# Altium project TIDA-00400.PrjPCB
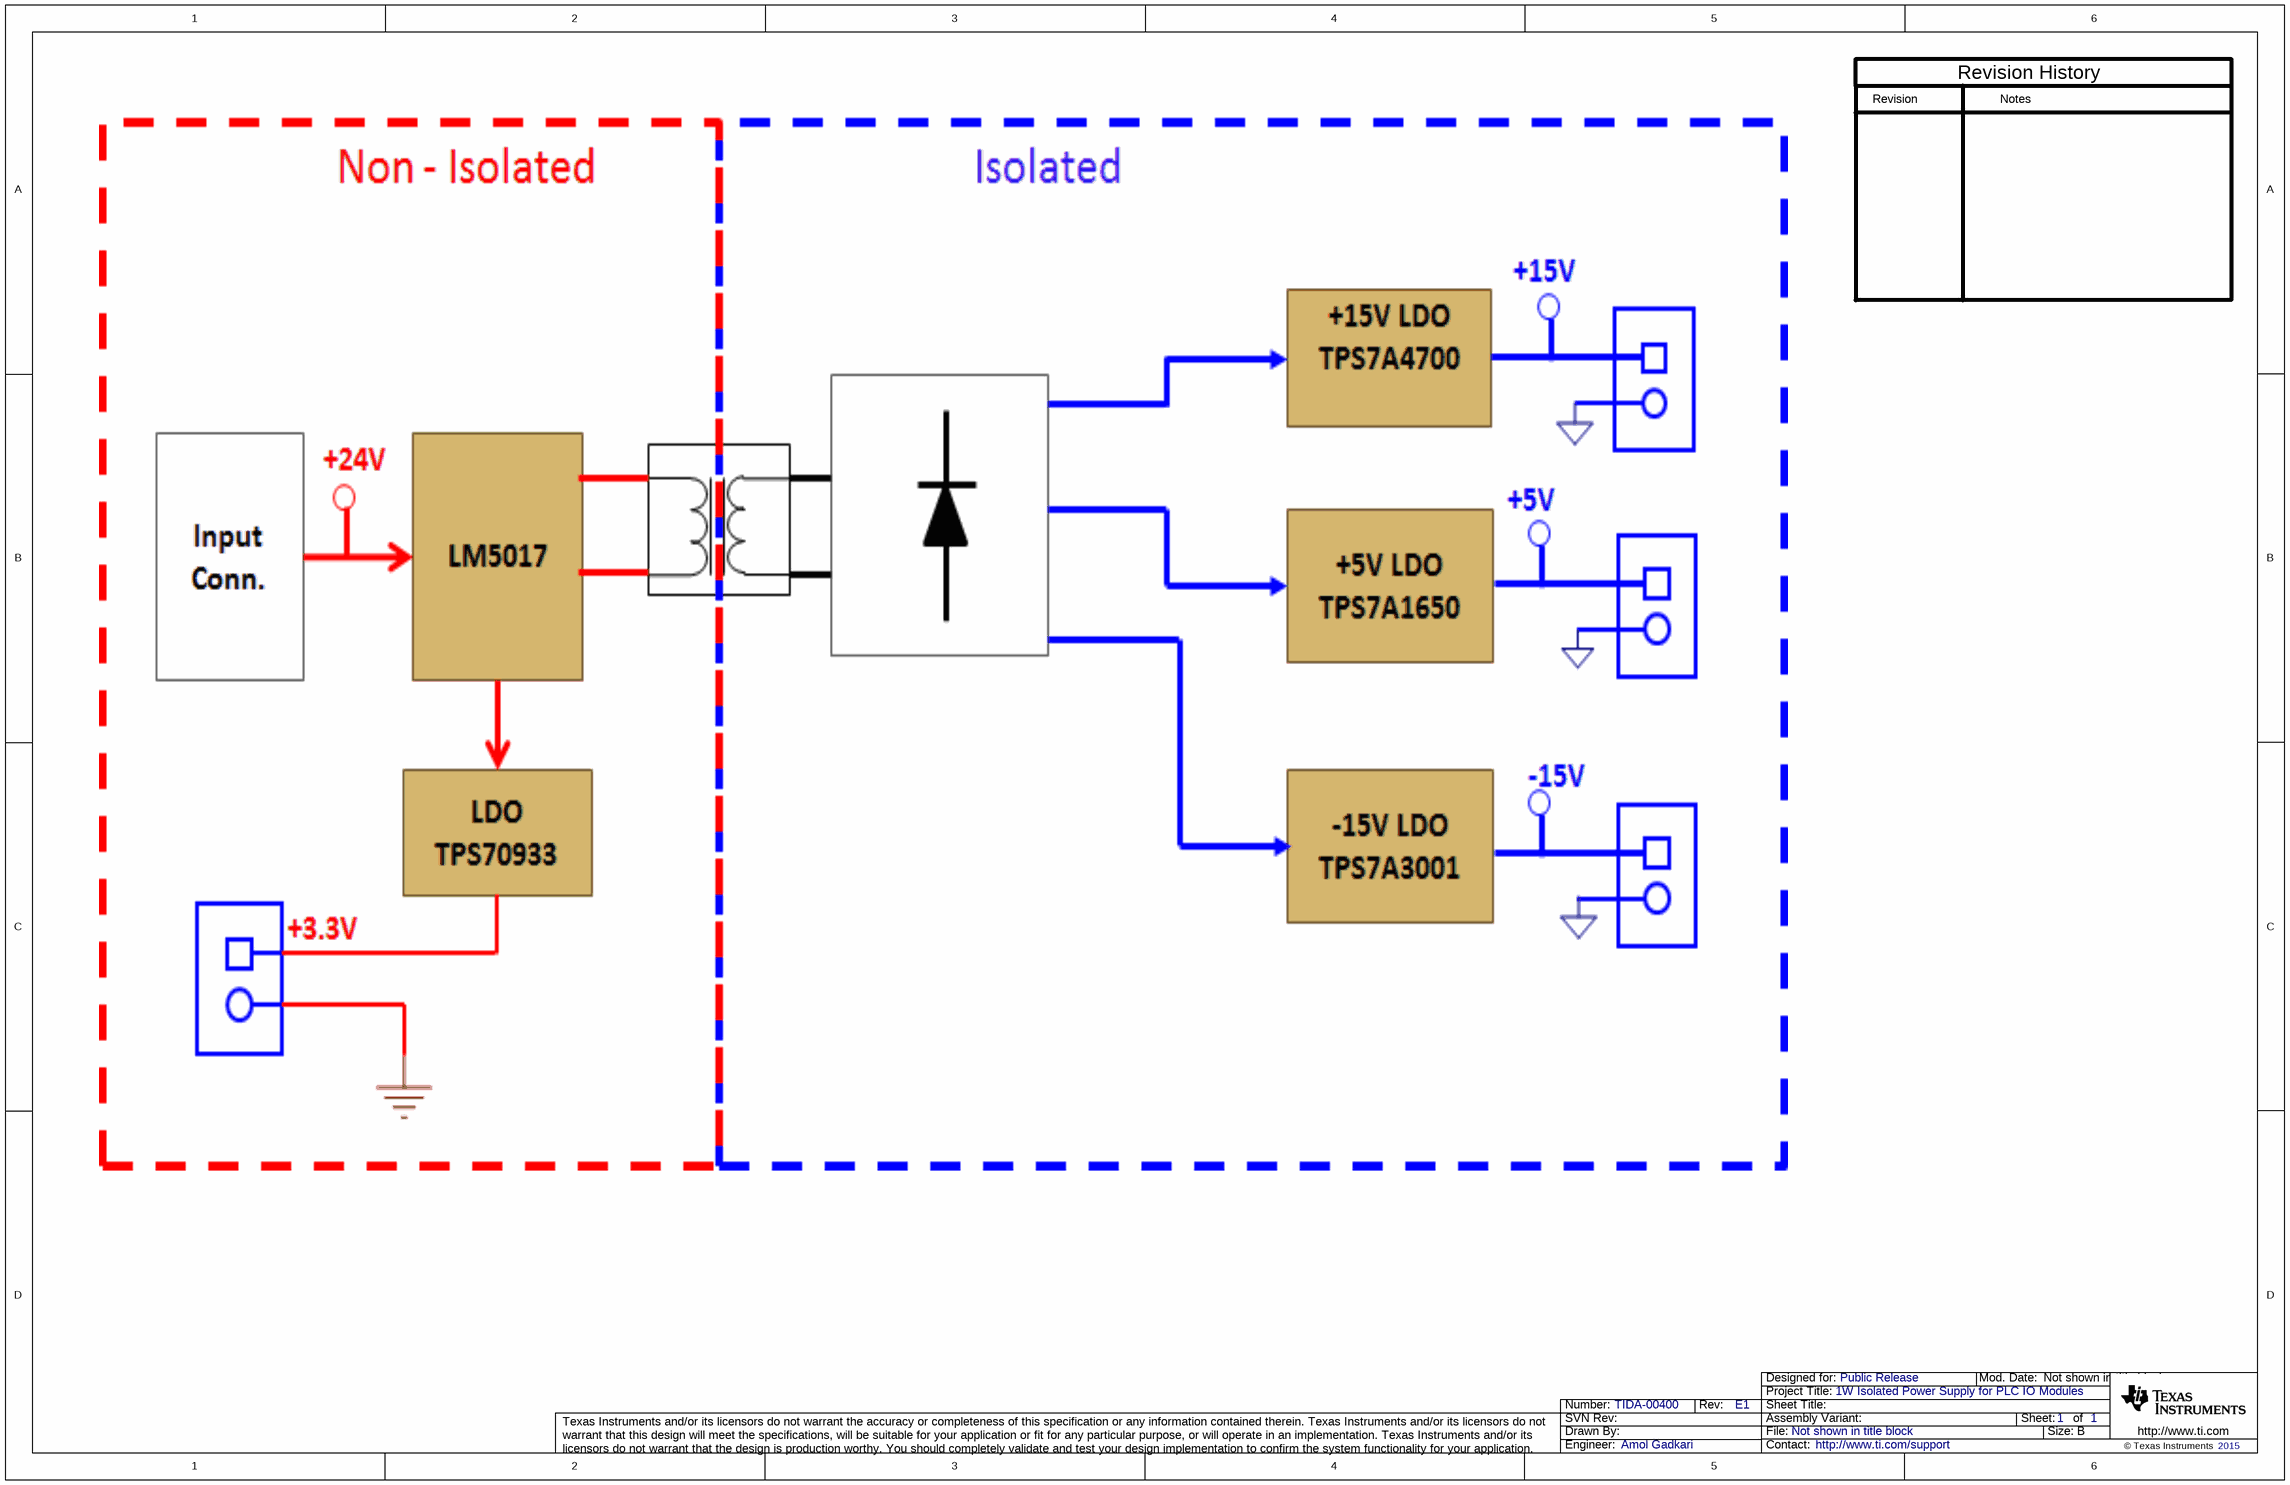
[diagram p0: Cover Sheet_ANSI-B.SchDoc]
CopyrightYear: 2015; PCB_Layout: Sharanu; PCB_Rev: E1; PRJ_Customer: Public Release; PRJ_Engineer: Amol Gadkari; PRJ_Number: TIDA-00400; PRJ_Title: 1W Isolated Power Supply for PLC IO Modules; SCH_Rev: E1; TechSupport: http://www.ti.com/support
4 sheets, 124 parts. Net scope: global (net labels, ports and power ports of the same name join across sheets).
Board file: TIDA-00400.PcbDoc
Sheets:
  Cover Sheet_ANSI-B.SchDoc
  Isolated_Flybuck_PS.SchDoc
  Post Regulated LDO.SchDoc
  Hardware_ANSI-B.SchDoc

## Sheet Cover Sheet_ANSI-B.SchDoc
size 431 x 279 mm; Date: Not shown in title block; ApprovedBy: Not shown in title block; CheckedBy: Not shown in title block; Author: Not shown in title block; CompanyName: Not shown in title block; Engineer: Not shown in title block; Organization: Not shown in title block; Address1: Not shown in title block; Address2: Not shown in title block; Address3: Not shown in title block; Address4: Not shown in title block; DocumentNumber: 1; Revision: Use project parameter SCH_Rev; SheetNumber: 1; SheetTotal: 1; PageSetup: Record=PageOptions|CenterHorizontal=True|CenterVertical=True|PrintScale=1.00|XCorrection=1.00|YCorrection=1.00|PrintKind=0|BorderSize=5000000|LeftOffset=0|BottomOffset=0|Orientation=2|PaperLength=1000|PaperWidth=1000|Scale=100|PaperSource=15|PrintQuality=600|MediaType=1|DitherType=10|PaperKind=Letter|PrintScaleMode=1

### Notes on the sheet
- Revision
- Notes
- Revision History

## Sheet Isolated_Flybuck_PS.SchDoc
size 431 x 279 mm; Date: Not shown in title block; ApprovedBy: Not shown in title block; CheckedBy: Not shown in title block; Author: Not shown in title block; CompanyName: Not shown in title block; Engineer: Not shown in title block; Organization: Not shown in title block; Address1: Not shown in title block; Address2: Not shown in title block; Address3: Not shown in title block; Address4: Not shown in title block; DocumentNumber: 1; Revision: Use project parameter SCH_Rev; SheetNumber: 1; SheetTotal: 1; PageSetup: Record=PageOptions|CenterHorizontal=True|CenterVertical=True|PrintScale=1.00|XCorrection=1.00|YCorrection=1.00|PrintKind=0|BorderSize=5000000|LeftOffset=0|BottomOffset=0|Orientation=2|PaperLength=1000|PaperWidth=1000|Scale=100|PaperSource=15|PrintQuality=600|MediaType=1|DitherType=10|PaperKind=Letter|PrintScaleMode=1
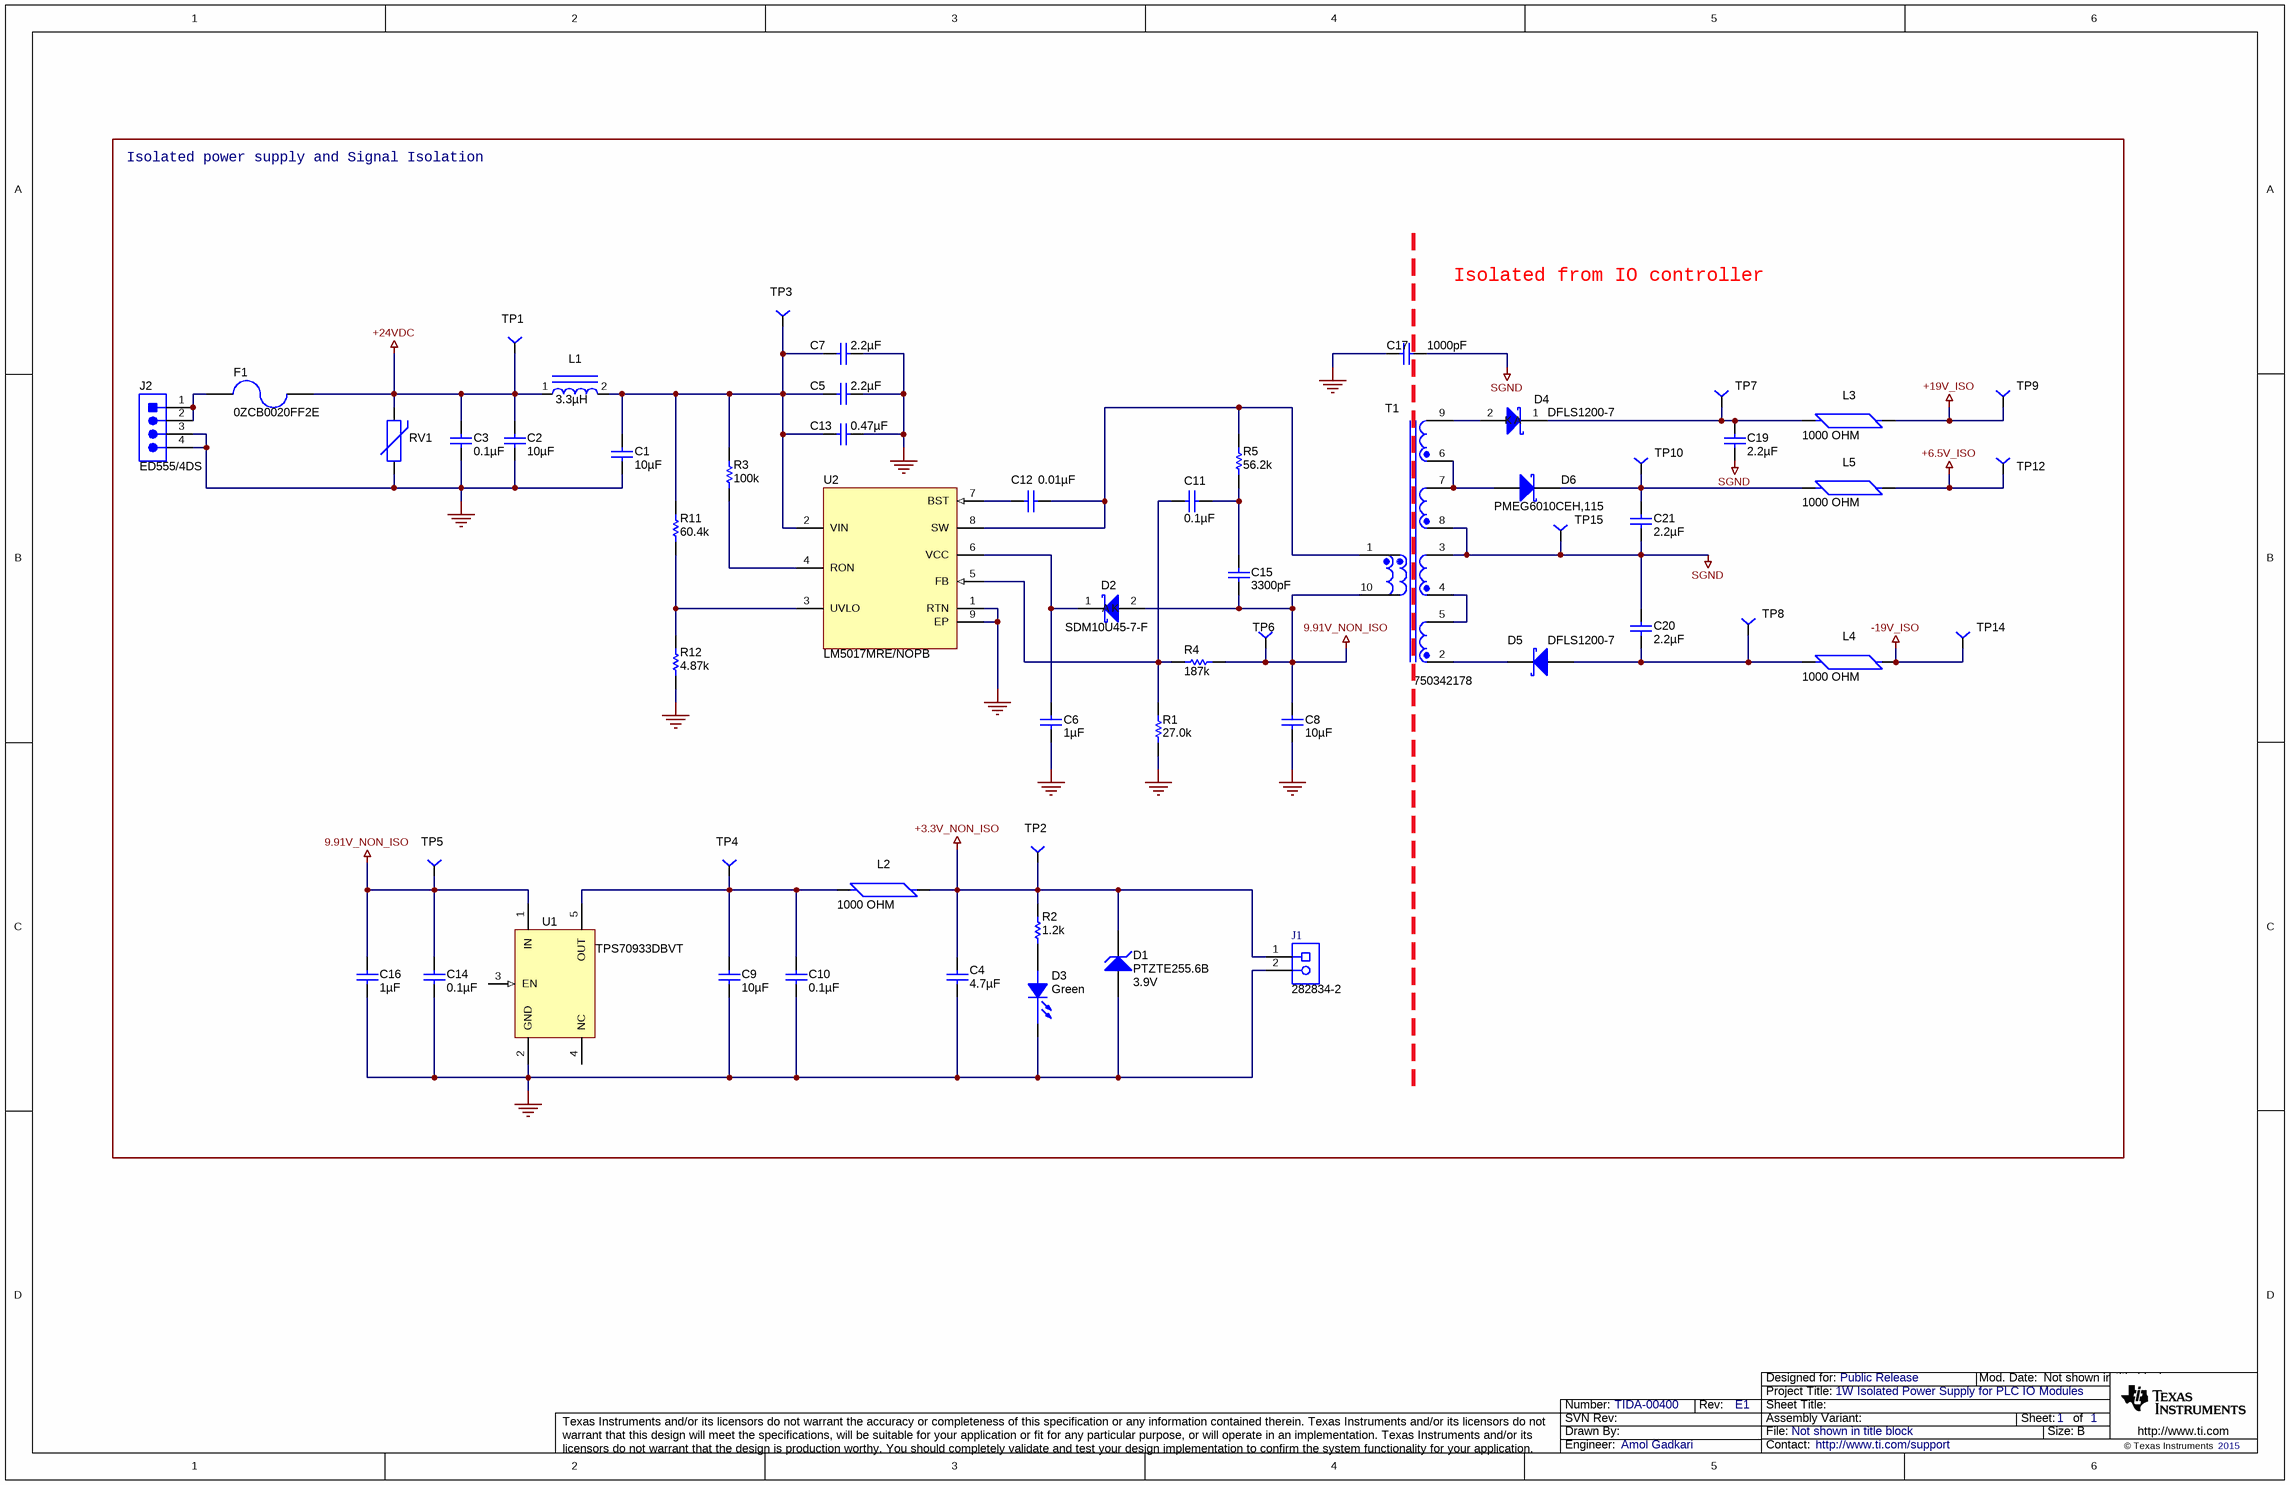
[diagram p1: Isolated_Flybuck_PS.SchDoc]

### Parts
C1  ValueDisplayed: 10µF  [1210]  (hidden comment: GRM32ER71H106KA12L)
C2  ValueDisplayed: 10µF  [1210]  (hidden comment: GRM32ER71H106KA12L)
C3  ValueDisplayed: 0.1µF  [0805]  (hidden comment: C0805C104K1RACTU)
C4  ValueDisplayed: 4.7µF  [0805_HV]  (hidden comment: C2012X5R1H475K125AB)
C5  ValueDisplayed: 2.2µF  [1210]  (hidden comment: GRM32ER72A225KA35L)
C6  ValueDisplayed: 1µF  [0603]  (hidden comment: GRM188R61H105KAALD)
C7  ValueDisplayed: 2.2µF  [1210]  (hidden comment: GRM32ER72A225KA35L)
C8  ValueDisplayed: 10µF  [1210]  (hidden comment: GMK325AB7106MM-T)
C9  ValueDisplayed: 10µF  [0805]  (hidden comment: 0805YD106MAT2A)
C10  ValueDisplayed: 0.1µF  [0603]  (hidden comment: C0603C104K5RACTU)
C11  ValueDisplayed: 0.1µF  [0603]  (hidden comment: GRM188R72A104KA35D)
C12  ValueDisplayed: 0.01µF  [0603]  (hidden comment: 06031C103JAT2A)
C13  ValueDisplayed: 0.47µF  [1206]  (hidden comment: GRM31MR72A474KA35L)
C14  ValueDisplayed: 0.1µF  [0603]  (hidden comment: C0603C104K5RACTU)
C15  ValueDisplayed: 3300pF  [0603]  (hidden comment: 06031C332JAT2A)
C16  ValueDisplayed: 1µF  [0805]  (hidden comment: 08055C105KAT2A)
C17  value 1000pF  [1206]  (hidden comment: 202R18W102KV4E)
C19  ValueDisplayed: 2.2µF  [0805_HV]  (hidden comment: GRM21BR71E225KA73L)
C20  ValueDisplayed: 2.2µF  [0805_HV]  (hidden comment: GRM21BR71E225KA73L)
C21  ValueDisplayed: 2.2µF  [0805_HV]  (hidden comment: GRM21BR71E225KA73L)
D1  PTZTE255.6B  value 3.9V  [powerDI123]
D2  SDM10U45-7-F  [SOD-523]
D3  value Green  [LED0603AA]  (hidden comment: LED_LG L29K-G2J1-24-Z)
D4  DFLS1200-7  [powerDI123]
D5  DFLS1200-7  [powerDI123]
D6  PMEG6010CEH,115  [SOD-123F]
F1  0ZCB0020FF2E  [1210]
J1  282834-2  [TEC_282834-2]
J2  ED555/4DS  [TERM_BLK_ED555-4DS]
L1  3.3µH  [IND_B82422H]
L2  1000 OHM  [FB0603]
L3  1000 OHM  [FB0603]
L4  1000 OHM  [FB0603]
L5  1000 OHM  [FB0603]
R1  value 27.0k  [0603]  (hidden comment: RC0603FR-0727KL)
R2  value 1.2k  [0402]  (hidden comment: CRCW04021K20JNED)
R3  value 100k  [0603]  (hidden comment: CRCW0603100KFKEA)
R4  value 187k  [0603]  (hidden comment: CRCW0603187KFKEA)
R5  value 56.2k  [0603]  (hidden comment: RT0603BRD0756K2L)
R11  value 60.4k  [0603]  (hidden comment: RT0603BRD0760K4L)
R12  value 4.87k  [0603]  (hidden comment: RC0603FR-074K87L)
RV1  VC080530A650DP  [1206]  (value not drawn)
T1  750342178  [WURTH_750313995]
TP1  TP1_PD40_D0.5_S50  [TP1_PD40_D0.5_S50]  (value not drawn)
TP2  TP1_PD40_D0.5_S50  [TP1_PD40_D0.5_S50]  (value not drawn)
TP3  TP1_PD40_D0.5_S50  [TP1_PD40_D0.5_S50]  (value not drawn)
TP4  TP1_PD40_D0.5_S50  [TP1_PD40_D0.5_S50]  (value not drawn)
TP5  TP1_PD40_D0.5_S50  [TP1_PD40_D0.5_S50]  (value not drawn)
TP6  TP1_PD40_D0.5_S50  [TP1_PD40_D0.5_S50]  (value not drawn)
TP7  TP1_PD40_D0.5_S50  [TP1_PD40_D0.5_S50]  (value not drawn)
TP8  TP1_PD40_D0.5_S50  [TP1_PD40_D0.5_S50]  (value not drawn)
TP9  TP1_PD40_D0.5_S50  [TP1_PD40_D0.5_S50]  (value not drawn)
TP10  TP1_PD40_D0.5_S50  [TP1_PD40_D0.5_S50]  (value not drawn)
TP12  TP1_PD40_D0.5_S50  [TP1_PD40_D0.5_S50]  (value not drawn)
TP14  TP1_PD40_D0.5_S50  [TP1_PD40_D0.5_S50]  (value not drawn)
TP15  TP1_PD40_D0.5_S50  [TP1_PD40_D0.5_S50]  (value not drawn)
U1  TPS70933DBVT  [DBV0005A_N]
U2  LM5017MRE/NOPB  [DDA0008B_N]

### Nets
9.91V_NON_ISO: C8.1 C14.1 C15.2 C16.1 D2.2(A) R4.2 T1.10 TP5.1 TP6.1 U1.1(IN)
+3.3V_NON_ISO: C4.2 D1.1(K) J1.1 L2.2 R2.1 TP2.1
+6.5V_ISO: L5.2 TP12.1
+19V_ISO: L3.2 TP9.1
+24VDC: C2.1 C3.1 F1.1 L1.1 RV1.2 TP1.1
-19V_ISO: L4.2 TP14.1
GND: C1.2 C2.2 C3.2 C4.1 C5.1 C6.2 C7.1 C8.2 C9.2 C10.2 C13.1 C14.2 C16.2 C17.1 D1.2(A) D3.1(C) J1.2 J2.3 J2.4 R1.1 R12.1 RV1.1 U1.2(GND) U2.1(RTN) U2.9(EP)
SGND: C17.2 C19.2 C20.1 C21.2 T1.3 T1.8 TP15.1
NetC1_1: C1.1 C5.2 C7.2 C13.2 L1.2 R3.2 R11.2 TP3.1 U2.2(VIN)
NetC6_1: C6.1 D2.1(K) U2.6(VCC)
NetC9_1: C9.1 C10.1 L2.1 TP4.1 U1.5(OUT)
NetC11_1: C11.1 C15.1 R5.1
NetC11_2: C11.2 R1.2 R4.1 U2.5(FB)
NetC12_1: C12.1 U2.7(BST)
NetC12_2: C12.2 R5.2 T1.1 U2.8(SW)
NetC19_1: C19.1 D4.1(K) L3.1 TP7.1
NetC20_2: C20.2 D5.2(A) L4.1 TP8.1
NetC21_1: C21.1 D6.1(K) L5.1 TP10.1
NetD3_2: D3.2(A) R2.2
NetD4_2: D4.2(A) T1.9
NetD5_1: D5.1(K) T1.2
NetD6_2: D6.2(A) T1.6 T1.7
NetF1_2: F1.2 J2.1 J2.2
NetR3_1: R3.1 U2.4(RON)
NetR11_1: R11.1 R12.2 U2.3(UVLO)
NetT1_4: T1.4 T1.5

Not connected (* = marked no-connect by the designer): U1 3(EN) 4(NC)

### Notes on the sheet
- Isolated power supply and Signal Isolation
- Isolated from IO controller

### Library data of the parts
C1 C2 = GRM32ER71H106KA12L: CAP, CERM, 10uF, 50V, +/-10%, X7R, 1210; Manufacturer: MuRata; Polarized: N; CompType: Capacitor; U/M: EA; Cap_F: 0.00001; Tolerance_%: 10; Value1: Unknown; VDC_V: 50; TaMin_C: -55; TaMax_C: 125
C3 = C0805C104K1RACTU: CAP, CERM, 0.1uF, 100V, +/-10%, X7R, 0805; Manufacturer: Kemet; Polarized: N; CompType: Capacitor; U/M: EA; Cap_F: 0.0000001; Tolerance_%: 10; ESR_Ohm: 0.064; Value1: 0.064 ohm; VDC_V: 100; IRMS_A: 1.64; TaMin_C: -55; TaMax_C: 125
C4 = C2012X5R1H475K125AB: CAP, CERM, 4.7uF, 50V, +/-10%, X5R, 0805; Manufacturer: TDK; Polarized: N; CompType: Capacitor; U/M: EA; Cap_F: 0.0000047; Tolerance_%: 10; Value1: Unknown; VDC_V: 50; TaMin_C: -55; TaMax_C: 85; Cap_Case: 0805
C5 C7 = GRM32ER72A225KA35L: CAP, CERM, 2.2uF, 100V, +/-10%, X7R, 1210; Manufacturer: MuRata; Polarized: N; CompType: Capacitor; U/M: EA; Cap_F: 0.0000022; Tolerance_%: 10; ESR_Ohm: 0.007; Value1: 0.007 ohm; VDC_V: 100; IRMS_A: 4.4; TaMin_C: -55; TaMax_C: 125
C6 = GRM188R61H105KAALD: CAP, CERM, 1uF, 50V, +/-10%, X5R, 0603; Manufacturer: MuRata; Polarized: N; CompType: Capacitor; U/M: EA; Cap_F: 0.000001; Tolerance_%: 10; Value1: Unknown; VDC_V: 50; TaMin_C: -55; TaMax_C: 85
C8 = GMK325AB7106MM-T: CAP, CERM, 10uF, 35V, +/-20%, X7R, 1210; Manufacturer: Taiyo Yuden; Polarized: N; CompType: Capacitor; U/M: EA; Cap_F: 0.00001; Tolerance_%: 20; Value1: Unknown; VDC_V: 35; TaMin_C: -55; TaMax_C: 125
C9 = 0805YD106MAT2A: CAP, CERM, 10uF, 16V, +/-20%, X5R, 0805; Manufacturer: AVX; Polarized: N; CompType: Capacitor; U/M: EA; Cap_F: 0.00001; Tolerance_%: 20; Value1: Unknown; VDC_V: 16; TaMin_C: -55; TaMax_C: 85
C10 C14 = C0603C104K5RACTU: CAP, CERM, 0.1uF, 50V, +/-10%, X7R, 0603; Manufacturer: Kemet; Polarized: N; CompType: Capacitor; U/M: EA; Cap_F: 0.0000001; Tolerance_%: 10; Value1: Unknown; VDC_V: 50; TaMin_C: -55; TaMax_C: 125
C11 = GRM188R72A104KA35D: CAP, CERM, 0.1uF, 100V, +/-10%, X7R, 0603; Manufacturer: MuRata; Polarized: N; CompType: Capacitor; U/M: EA; Cap_F: 0.0000001; Tolerance_%: 10; Value1: Unknown; VDC_V: 100; TaMin_C: -55; TaMax_C: 125
C12 = 06031C103JAT2A: CAP, CERM, 0.01uF, 100V, +/-5%, X7R, 0603; Manufacturer: AVX; Polarized: N; CompType: Capacitor; U/M: EA; Cap_F: 0.00000001; Tolerance_%: 5; ESR_Ohm: 0.098; Value1: 0.098 ohm; VDC_V: 100; TaMin_C: -55; TaMax_C: 125
C13 = GRM31MR72A474KA35L: CAP, CERM, 0.47uF, 100V, +/-10%, X7R, 1206; Manufacturer: MuRata; Polarized: N; CompType: Capacitor; U/M: EA; Cap_F: 0.00000047; Tolerance_%: 10; Value1: Unknown; VDC_V: 100; TaMin_C: -55; TaMax_C: 125
C15 = 06031C332JAT2A: CAP, CERM, 3300pF, 100V, +/-5%, X7R, 0603; Manufacturer: AVX; Polarized: N; CompType: Capacitor; U/M: EA; Cap_F: 0.0000000033; Tolerance_%: 5; ESR_Ohm: 0.159; Value1: 0.159 ohm; VDC_V: 100; TaMin_C: -55; TaMax_C: 125
C16 = 08055C105KAT2A: CAP, CERM, 1uF, 50V, +/-10%, X7R, 0805; Manufacturer: AVX; Polarized: N; CompType: Capacitor; U/M: EA; Cap_F: 0.000001; Tolerance_%: 10; Value1: Unknown; VDC_V: 50; TaMin_C: -55; TaMax_C: 125
C17 = 202R18W102KV4E: CAP, CERM, 1000pF, 2KV 10% X7R 1206; Manufacturer: Johanson Dielectrics Inc; Polarized: N; CompType: Capacitor; Cap_F: 0.000000001; Tolerance_%: 0
C19-C21 = GRM21BR71E225KA73L: CAP, CERM, 2.2uF, 25V, +/-10%, X7R, 0805; Manufacturer: MuRata; Polarized: N; CompType: Capacitor; U/M: EA; Cap_F: 0.0000022; Tolerance_%: 10; ESR_Ohm: 0.005; Value1: 0.005 ohm; VDC_V: 25; TaMin_C: -55; TaMax_C: 125; Cap_Case: 0805
D1 = PTZTE255.6B: DIODE ZENER 3.9V 1W PMDS; PartNumber: PTZTE253.9B; Manufacturer: Rohm Semiconductor; U/M: EA; Vz_V: 3.9
D2 = SDM10U45-7-F: Diode, Schottky, 45V, 0.1A, SOD-523; Manufacturer: Diodes Inc.; U/M: EA; Vf_V: 0.58; Value2: 0.58V; Io_A: 0.1; Vr_V: 45; TJmax_C: 125
D3 = LED_LG L29K-G2J1-24-Z: LED SmartLED Green 570NM; Manufacturer: OSRAM; SymbolCreator: x0120606
D4 D5 = DFLS1200-7: Diode, Schottky, 200V, 1A, PowerDI123; Manufacturer: Diodes Inc.; U/M: EA; Vf_V: 0.85; Value2: 0.85V; Io_A: 1; Vr_V: 200; TJmax_C: 175; RJC_CperW: 7
D6 = PMEG6010CEH,115: Diode, Schottky, 60V, 1A, SOD-123F; Manufacturer: NXP Semiconductor; U/M: EA; Vf_V: 0.57; Value2: 0.57V; Io_A: 1; Vr_V: 60; TJmax_C: 150
F1 = 37215000001: PTC RESTTBLE 0.2A 60V CHIP 1210; Manufacturer: Bel Fuse Inc; CompType: Fuse; U/M: EA; OpeningTime_100%_min: 4; OpeningTime_200%_max: 2; VDC_V: 60; Irating_A: 5; MeltingTyp: 94; Vdrop: 0.08; Soldering_Wave_MaxTemp_C: 260
J1 = 282834-2: Terminal Block, 2x1, 2.54mm, TH; Manufacturer: TE Connectivity; SymbolCreator: a0412235; U/M: EA
J2 = ED555/4DS: Terminal Block, 6A, 3.5mm Pitch, 4-Pos, TH; Manufacturer: On-Shore Technology; SymbolCreator: a0412235; CompType: Connector; U/M: EA
L1 = IND_ELJEA_SERIES: Inductor, Chip, ±10%; Manufacturer: EPCOS INC.; PartNumber: B82422H1332K; Area: 28000; Description: INDUCTOR 3.3UH 770MA 1210 10%
L2-L5 = MMZ1608B102C: FERRITE CHIP 1000 OHM 300MA 0603; Manufacturer: TDK Corporation; CompType: Ferrite Bead
R1 = RC0603FR-0727KL: RES, 27.0k ohm, 1%, 0.1W, 0603; Manufacturer: Yageo America; CompType: Resistor; Res_ohm: 27000; Value_Code: 27k0; Tolerance_%: 1; Power_W: 0.1; VDC_V: 150; TempCo: 200 ppm/C; U/M: EA
R2 = CRCW04021K20JNED: RES, 1.2k ohm, 5%, 0.063W, 0402; Manufacturer: Vishay-Dale; CompType: Resistor; Res_ohm: 1200; Value_Code: 1k20; Tolerance_%: 5; Power_W: 0.063; VDC_V: 50; TempCo: 200 ppm/C; EIA_Code: E24; U/M: EA
R3 = CRCW0603100KFKEA: RES, 100k ohm, 1%, 0.1W, 0603; Manufacturer: Vishay-Dale; CompType: Resistor; Res_ohm: 100000; Tolerance_%: 1; Power_W: 0.1; VDC_V: 75; TempCo: 100 ppm/C; EIA_Code: E96; U/M: EA
R4 = CRCW0603187KFKEA: RES, 187k ohm, 1%, 0.1W, 0603; Manufacturer: Vishay-Dale; CompType: Resistor; Res_ohm: 187000; Tolerance_%: 1; Power_W: 0.1; VDC_V: 75; TempCo: 100 ppm/C; EIA_Code: E96; U/M: EA
R5 = RT0603BRD0756K2L: RES, 56.2k ohm, 0.1%, 0.1W, 0603; Manufacturer: Yageo America; CompType: Resistor; Res_ohm: 56200; Value_Code: 56k2; Tolerance_%: 0.1; VDC_V: 75; TempCo: 25 ppm/C; EIA_Code: E192; U/M: EA
R11 = RT0603BRD0760K4L: RES, 60.4k ohm, 0.1%, 0.1W, 0603; Manufacturer: Yageo America; CompType: Resistor; Res_ohm: 60400; Value_Code: 60k4; Tolerance_%: 0.1; VDC_V: 75; TempCo: 25 ppm/C; EIA_Code: E192; U/M: EA
R12 = RC0603FR-074K87L: RES, 4.87k ohm, 1%, 0.1W, 0603; Manufacturer: Yageo America; CompType: Resistor; Res_ohm: 4870; Value_Code: 4k87; Tolerance_%: 1; Power_W: 0.1; VDC_V: 150; TempCo: 200 ppm/C; EIA_Code: E96; U/M: EA
RV1 = VC120648D101DP: VARISTOR 36.9V 30A 0805; Manufacturer: AVX; SymbolCreator: a0412235
T1 = 750313995: Transformer, 50uH, SMT; Manufacturer: Wurth Elektronik eiSos; SymbolCreator: a0411947; DCR_Ohm: 0.11; LeakageL: 0.130uH; U/M: EA
TP1-TP10 TP12 TP14 TP15 = TP-040_RND: Test Point 40mil pad 20mil drill; Manufacturer: STD; Description: Test Point, O.040 Hole; Value: STD
U1 = TPS70933DBVT: IC REG LDO 3.3V 0.15A SOT23-5; Alternate Manufacturer: None; Manufacturer: Texas Instruments; SymbolCreator: a0411947; U/M: EA
U2 = LM5017MRE/NOPB: 100V, 600mA Constant On-Time Synchronous Buck Regulator, DDA0008B; Alternate Manufacturer: None; Manufacturer: Texas Instruments; SymbolCreator: a0412235; CompType: IC; U/M: EA

## Sheet Post Regulated LDO.SchDoc
size 431 x 279 mm; Date: Not shown in title block; ApprovedBy: Not shown in title block; CheckedBy: Not shown in title block; Author: Not shown in title block; CompanyName: Not shown in title block; Engineer: Not shown in title block; Organization: Not shown in title block; Address1: Not shown in title block; Address2: Not shown in title block; Address3: Not shown in title block; Address4: Not shown in title block; DocumentNumber: 1; Revision: Use project parameter SCH_Rev; SheetNumber: 1; SheetTotal: 1; PageSetup: Record=PageOptions|CenterHorizontal=True|CenterVertical=True|PrintScale=1.00|XCorrection=1.00|YCorrection=1.00|PrintKind=0|BorderSize=5000000|LeftOffset=0|BottomOffset=0|Orientation=2|PaperLength=1000|PaperWidth=1000|Scale=100|PaperSource=15|PrintQuality=600|MediaType=1|DitherType=10|PaperKind=Letter|PrintScaleMode=1
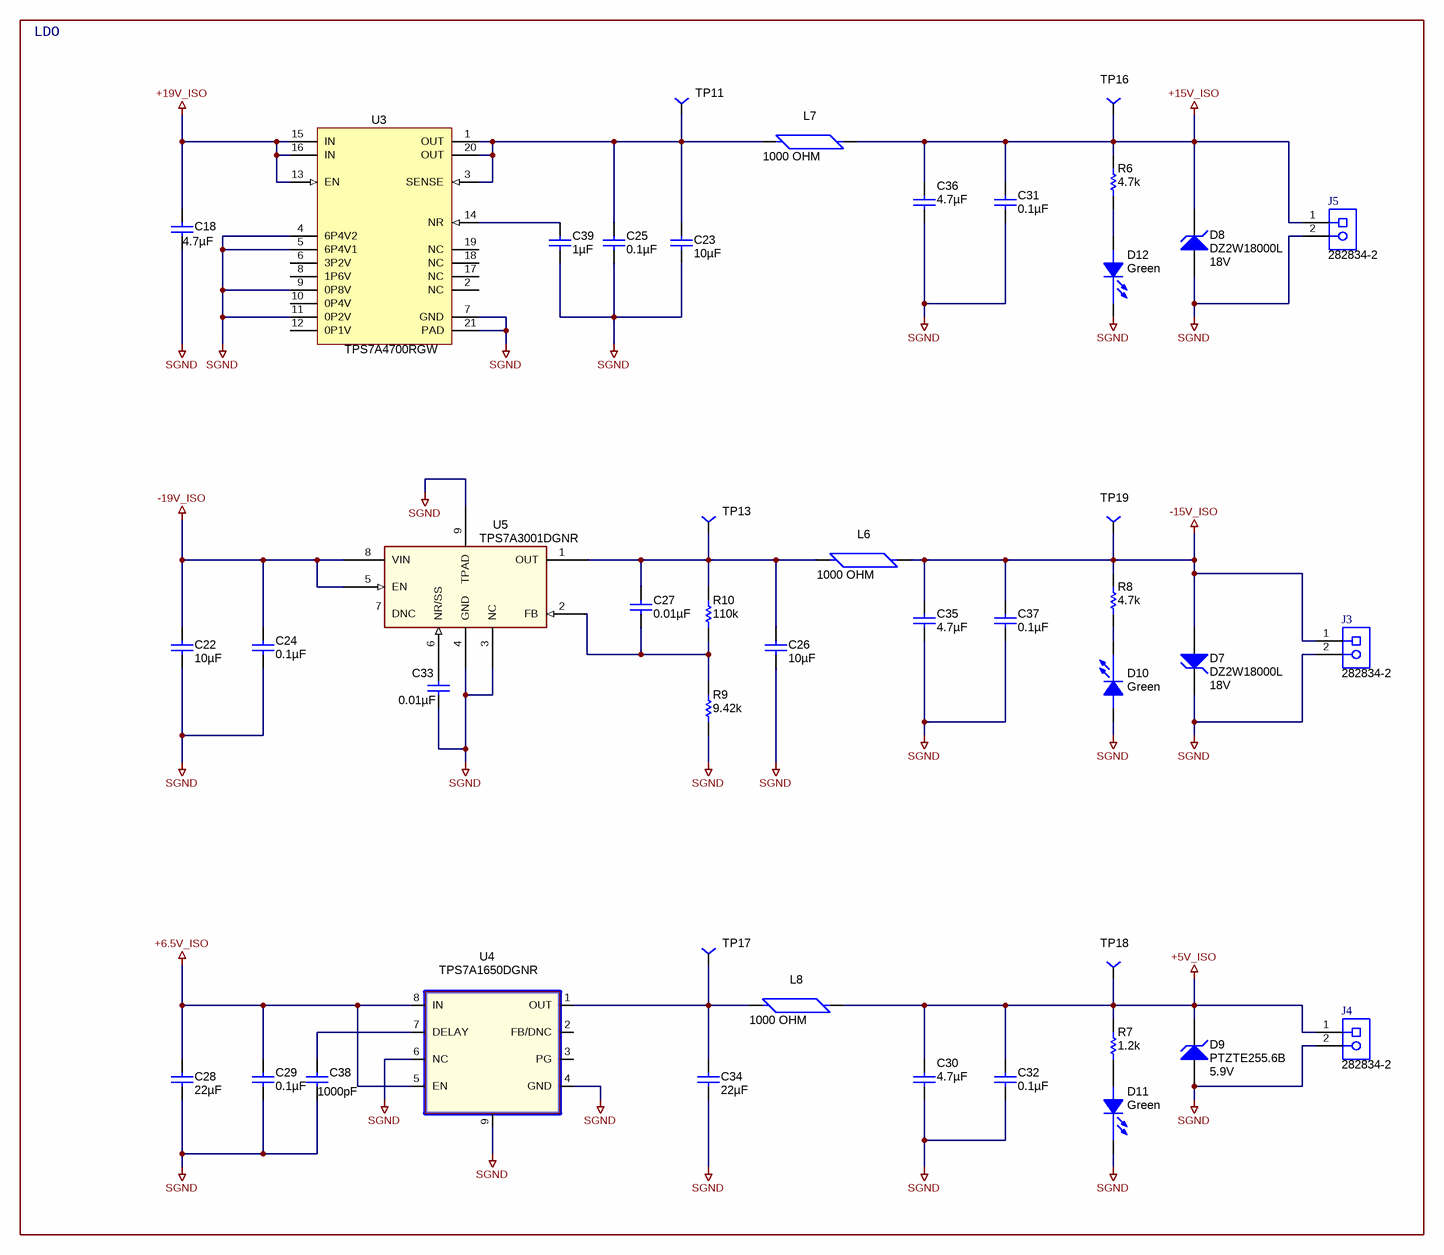
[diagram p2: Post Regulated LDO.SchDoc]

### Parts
C18  ValueDisplayed: 4.7µF  [1206]  (hidden comment: GRM31CR71H475KA12L)
C22  ValueDisplayed: 10µF  [1206]  (hidden comment: GRM31CR71E106KA12L)
C23  ValueDisplayed: 10µF  [1206]  (hidden comment: GRM31CR71E106KA12L)
C24  ValueDisplayed: 0.1µF  [0603]  (hidden comment: 06035C104KAT2A)
C25  ValueDisplayed: 0.1µF  [0603]  (hidden comment: 06035C104KAT2A)
C26  ValueDisplayed: 10µF  [1206]  (hidden comment: GRM31CR71E106KA12L)
C27  ValueDisplayed: 0.01µF  [0603]  (hidden comment: 06031C103JAT2A)
C28  ValueDisplayed: 22µF  [0805_HV]  (hidden comment: GRM21BR61C226ME44)
C29  ValueDisplayed: 0.1µF  [0603]  (hidden comment: 06035C104KAT2A)
C30  ValueDisplayed: 4.7µF  [0805_HV]  (hidden comment: C2012X5R1H475K125AB)
C31  ValueDisplayed: 0.1µF  [0603]  (hidden comment: 06035C104KAT2A)
C32  ValueDisplayed: 0.1µF  [0603]  (hidden comment: 06035C104KAT2A)
C33  ValueDisplayed: 0.01µF  [0603]  (hidden comment: 06031C103JAT2A)
C34  ValueDisplayed: 22µF  [0805_HV]  (hidden comment: GRM21BR61C226ME44)
C35  ValueDisplayed: 4.7µF  [0805_HV]  (hidden comment: C2012X5R1H475K125AB)
C36  ValueDisplayed: 4.7µF  [0805_HV]  (hidden comment: C2012X5R1H475K125AB)
C37  ValueDisplayed: 0.1µF  [0603]  (hidden comment: 06035C104KAT2A)
C38  ValueDisplayed: 1000pF  [0603]  (hidden comment: 06031C102JAT2A)
C39  ValueDisplayed: 1µF  [0603]  (hidden comment: C1608X7R1E105K080AB)
D7  DZ2W18000L  value 18V  [SOD-123]
D8  DZ2W18000L  value 18V  [SOD-123]
D9  PTZTE255.6B  value 5.9V  [powerDI123]
D10  value Green  [LED0603AA]  (hidden comment: LED_LG L29K-G2J1-24-Z)
D11  value Green  [LED0603AA]  (hidden comment: LED_LG L29K-G2J1-24-Z)
D12  value Green  [LED0603AA]  (hidden comment: LED_LG L29K-G2J1-24-Z)
J3  282834-2  [TEC_282834-2]
J4  282834-2  [TEC_282834-2]
J5  282834-2  [TEC_282834-2]
L6  1000 OHM  [FB0603]
L7  1000 OHM  [FB0603]
L8  1000 OHM  [FB0603]
R6  value 4.7k  [0603]  (hidden comment: CRCW06034K70JNEA)
R7  value 1.2k  [0402]  (hidden comment: CRCW04021K20JNED)
R8  value 4.7k  [0603]  (hidden comment: CRCW06034K70JNEA)
R9  value 9.42k  [0402]  (hidden comment: TNPW04029K42BEED)
R10  value 110k  [0402]  (hidden comment: CRCW0402110KFKED)
TP11  TP1_PD40_D0.5_S50  [TP1_PD40_D0.5_S50]  (value not drawn)
TP13  TP1_PD40_D0.5_S50  [TP1_PD40_D0.5_S50]  (value not drawn)
TP16  TP-038  [TP1_PD40_D0.5_S50]  (value not drawn)
TP17  TP1_PD40_D0.5_S50  [TP1_PD40_D0.5_S50]  (value not drawn)
TP18  TP-038  [TP1_PD40_D0.5_S50]  (value not drawn)
TP19  TP-038  [TP1_PD40_D0.5_S50]  (value not drawn)
U3  TPS7A4700RGW  [RGW0020A]
U4  TPS7A1650DGNR  [DGN_8P]
U5  TPS7A3001DGNR  [MSOP8(DGN)]

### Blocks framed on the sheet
LDO: C18 C22-C39 D7-D12 J3-J5 L6-L8 R6-R10 TP11 TP13 TP16-TP19 U3-U5

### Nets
+5V_ISO: C30.1 C32.2 D9.1(K) J4.1 L8.2 R7.1 TP18.1
+6.5V_ISO: C28.1 C29.2 U4.5(EN) U4.8(IN)
+15V_ISO: C31.2 C36.1 D8.1(K) J5.1 L7.2 R6.1 TP16.1
+19V_ISO: C18.1 U3.13(EN) U3.15(IN) U3.16(IN)
-15V_ISO: C35.2 C37.2 D7.2(A) J3.1 L6.2 R8.1 TP19.1
-19V_ISO: C22.1 C24.2 U5.5(EN) U5.8(VIN)
SGND: C18.2 C22.2 C23.2 C24.1 C25.1 C26.2 C28.2 C29.1 C30.2 C31.1 C32.1 C33.2 C34.2 C35.1 C36.2 C37.1 C38.2 C39.2 D7.1(K) D8.2(A) D9.2(A) D10.2(A) D11.1(C) D12.1(C) J3.2 J4.2 J5.2 R9.2 U3.4(6P4V2) U3.5(6P4V1) U3.7(GND) U3.9(0P8V) U3.11(0P2V) U3.21(PAD) U4.4(GND) U4.6(NC) U4.9 U5.3(NC) U5.4(GND) U5.9(TPAD)
NetC23_1: C23.1 C25.2 L7.1 TP11.1 U3.1(OUT) U3.3(SENSE) U3.20(OUT)
NetC26_1: C26.1 C27.1 L6.1 R10.1 TP13.1 U5.1(OUT)
NetC27_2: C27.2 R9.1 R10.2 U5.2(FB)
NetC33_1: C33.1 U5.6(NR/SS)
NetC34_1: C34.1 L8.1 TP17.1 U4.1(OUT)
NetC38_1: C38.1 U4.7(DELAY)
NetC39_1: C39.1 U3.14(NR)
NetD10_1: D10.1(C) R8.2
NetD11_2: D11.2(A) R7.2
NetD12_2: D12.2(A) R6.2

Not connected (* = marked no-connect by the designer): U3 2(NC) 6(3P2V) 8(1P6V) 10(0P4V) 12(0P1V) 17(NC) 18(NC) 19(NC); U4 2(FB/DNC) 3(PG); U5 7(DNC)

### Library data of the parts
C18 = GRM31CR71H475KA12L: CAP, CERM, 4.7uF, 50V, +/-10%, X7R, 1206; Manufacturer: MuRata; Polarized: N; CompType: Capacitor; U/M: EA; Cap_F: 0.0000047; Tolerance_%: 10; Value1: Unknown; VDC_V: 50; TaMin_C: -55; TaMax_C: 125; Cap_Case: 2220
C22 C23 C26 = GRM31CR71E106KA12L: CAP, CERM, 10uF, 25V, +/-10%, X7R, 1206; Manufacturer: MuRata; Polarized: N; CompType: Capacitor; U/M: EA; Cap_F: 0.00001; Tolerance_%: 10; Value1: Unknown; VDC_V: 25; TaMin_C: -55; TaMax_C: 125; Cap_Case: 2220
C24 C25 C29 C31 C32 C37 = 06035C104KAT2A: CAP, CERM, 0.1uF, 50V, +/-10%, X7R, 0603; Manufacturer: AVX; Polarized: N; CompType: Capacitor; U/M: EA; Cap_F: 0.0000001; Tolerance_%: 10; Value1: Unknown; VDC_V: 50; TaMin_C: -55; TaMax_C: 125
C27 C33 = 06031C103JAT2A: as C12 on sheet Isolated_Flybuck_PS
C28 C34 = GRM21BR61C226ME44: CAP, CERM, 22uF, 16V, +/-20%, X5R, 0805; Manufacturer: MuRata; Polarized: N; CompType: Capacitor; U/M: EA; Cap_F: 0.000022; Tolerance_%: 20; Value1: Unknown; VDC_V: 16; TaMin_C: -55; TaMax_C: 85; Cap_Case: 0805
C30 C35 C36 = C2012X5R1H475K125AB: as C4 on sheet Isolated_Flybuck_PS
C38 = 06031C102JAT2A: CAP, CERM, 1000pF, 100V, +/-5%, X7R, 0603; Manufacturer: AVX; Polarized: N; CompType: Capacitor; U/M: EA; Cap_F: 0.000000001; Tolerance_%: 5; ESR_Ohm: 0.276; Value1: 0.276 ohm; VDC_V: 100; TaMin_C: -55; TaMax_C: 125
C39 = C1608X7R1E105K080AB: CAP, CERM, 1uF, 25V, +/-10%, X7R, 0603; Manufacturer: TDK; Polarized: N; CompType: Capacitor; U/M: EA; Cap_F: 0.000001; Tolerance_%: 10; Value1: Unknown; VDC_V: 25; TaMin_C: -55; TaMax_C: 125
D7 D8 = DZ2W18000L: Diode, Zener, 18V, 1W, SOD-123; Manufacturer: Panasonic
D9 = PTZTE255.6B: DIODE ZENER 5.9V 1W PMDS; Manufacturer: Rohm Semiconductor; U/M: EA; Vz_V: 5.9
D10-D12 = LED_LG L29K-G2J1-24-Z: as D3 on sheet Isolated_Flybuck_PS
J3-J5 = 282834-2: as J1 on sheet Isolated_Flybuck_PS
L6-L8 = MMZ1608B102C: as L2 on sheet Isolated_Flybuck_PS
R6 R8 = CRCW06034K70JNEA: RES, 4.7k ohm, 5%, 0.1W, 0603; Manufacturer: Vishay-Dale; CompType: Resistor; Res_ohm: 4700; Value_Code: 4k70; Tolerance_%: 5; Power_W: 0.1; VDC_V: 75; TempCo: 200 ppm/C; EIA_Code: E24; U/M: EA
R7 = CRCW04021K20JNED: as R2 on sheet Isolated_Flybuck_PS
R9 = CRCW04029K31FKED: RES, 9.42k ohm, 1%, 0.063W, 0402; Manufacturer: Vishay-Dale; CompType: Resistor; Res_ohm: 9310; Value_Code: 9k42; Tolerance_%: 1; Power_W: 0.063; VDC_V: 50; TempCo: 100 ppm/C; EIA_Code: E96; U/M: EA
R10 = CRCW0402110KFKED: RES, 110k ohm, 1%, 0.063W, 0402; Manufacturer: Vishay-Dale; CompType: Resistor; Res_ohm: 110000; Tolerance_%: 1; Power_W: 0.063; VDC_V: 50; TempCo: 100 ppm/C; EIA_Code: E96; U/M: EA
TP11 TP13 TP17 = TP-040_RND: as TP1 on sheet Isolated_Flybuck_PS
TP16 TP18 TP19 = TP-038: Test Point 40mil pad 20mil drill; Manufacturer: STD; Value: STD
U3 = TPS7A4700RGW: 36-V, 1-A, 4.17-µVRMS, RF LDO Voltage Regulator, RGW0020A; Alternate Manufacturer: None; Manufacturer: Texas Instruments; SymbolCreator: a0412235; CompType: IC; U/M: EA
U4 = TPS7A16XXDGN: IC, 60-V, 6-A IQ, 100-mA, LDO Voltage Regulator with Enable and Power-Good Functions; Manufacturer: TI; Alternate Manufacturer: None; Area: 35250
U5 = TPS7A3001DGNR: -36V, -200mA, Ultralow-Noise, Negative Linear Regulator; Alternate Manufacturer: None; Manufacturer: Texas Instruments; CompType: IC; SymbolCreator: x0120606

## Sheet Hardware_ANSI-B.SchDoc
size 431 x 279 mm; Date: Not shown in title block; ApprovedBy: Not shown in title block; CheckedBy: Not shown in title block; Author: Not shown in title block; CompanyName: Not shown in title block; Engineer: Not shown in title block; Organization: Not shown in title block; Address1: Not shown in title block; Address2: Not shown in title block; Address3: Not shown in title block; Address4: Not shown in title block; DocumentNumber: 1; Revision: Use project parameter SCH_Rev; SheetNumber: 1; SheetTotal: 1; PageSetup: Record=PageOptions|CenterHorizontal=True|CenterVertical=True|PrintScale=1.00|XCorrection=1.00|YCorrection=1.00|PrintKind=0|BorderSize=5000000|LeftOffset=0|BottomOffset=0|Orientation=2|PaperLength=1000|PaperWidth=1000|Scale=100|PaperSource=15|PrintQuality=600|MediaType=1|DitherType=10|PaperKind=Letter|PrintScaleMode=1
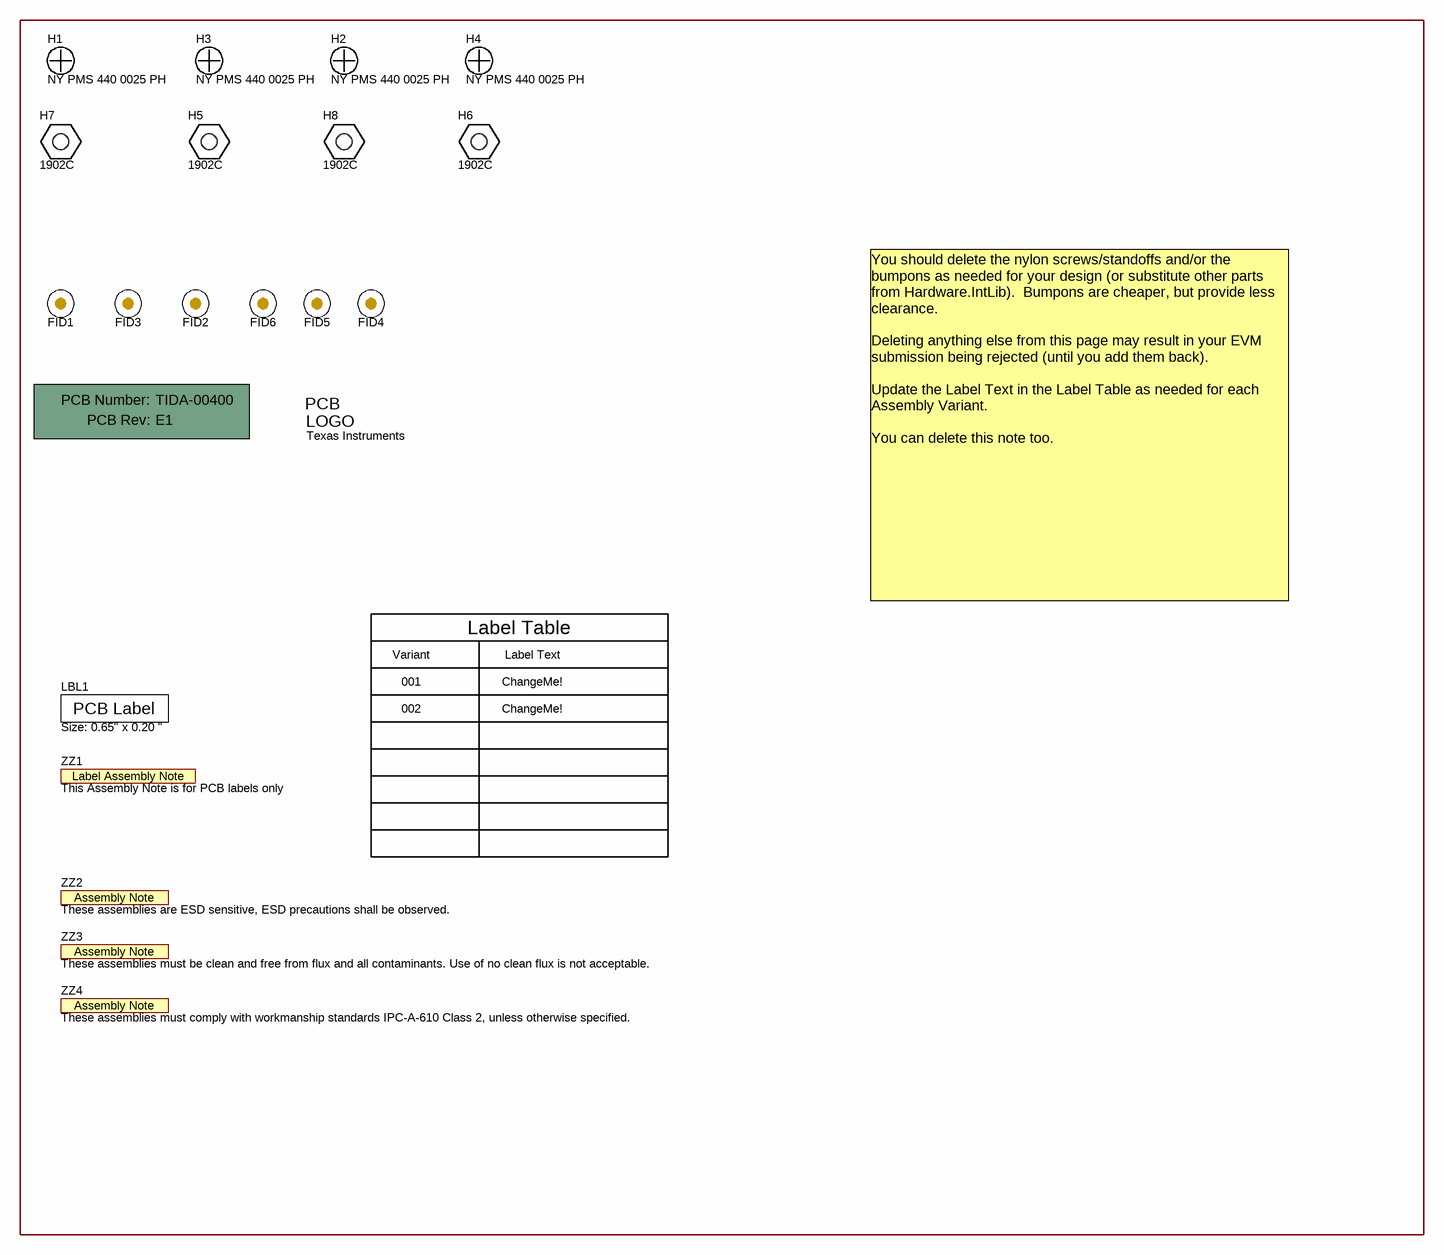
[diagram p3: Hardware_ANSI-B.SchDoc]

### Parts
!PCB1  Printed Circuit Board  (value not drawn)  (mechanical)
FID1  Fiducial  [Fiducial10-20]  (value not drawn)
FID2  Fiducial  [Fiducial10-20]  (value not drawn)
FID3  Fiducial  [Fiducial10-20]  (value not drawn)
FID4  Fiducial  [Fiducial10-20]  (value not drawn)
FID5  Fiducial  [Fiducial10-20]  (value not drawn)
FID6  Fiducial  [Fiducial10-20]  (value not drawn)
H1  NY PMS 440 0025 PH  [NY PMS 440 0025 PH]
H2  NY PMS 440 0025 PH  [NY PMS 440 0025 PH]
H3  NY PMS 440 0025 PH  [NY PMS 440 0025 PH]
H4  NY PMS 440 0025 PH  [NY PMS 440 0025 PH]
H5  1902C  [Keystone_1902C]
H6  1902C  [Keystone_1902C]
H7  1902C  [Keystone_1902C]
H8  1902C  [Keystone_1902C]
LBL1  Size: 0.65" x 0.20 "  [Label_650x200]
Logo1  Texas Instruments  [TI_Stacked_SolderMask_Small]  (no BOM)
ZZ1  This Assembly Note is for PCB labels only  [AssemblyNoteLabel]  (no BOM)
ZZ2  These assemblies are ESD sensitive, ESD precautions shall be observed.  [AssemblyNote]  (no BOM)
ZZ3  These assemblies must be clean and free from flux and all contaminants. Use of no clean flux is not acceptable.  [AssemblyNote]  (no BOM)
ZZ4  These assemblies must comply with workmanship standards IPC-A-610 Class 2, unless otherwise specified.  [AssemblyNote]  (no BOM)

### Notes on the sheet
- Variant
- Label Table
- Label Text
- You should delete the nylon screws/standoffs and/or the bumpons as needed for your design (or substitute other parts from Hardware.IntLib).  Bumpons are cheaper, but provide less clearance.
  Deleting anything else from this page may result in your EVM submission being rejected (until you add them back).
  Update the Label Text in the Label Table as needed for each Assembly Variant.
  You can delete this note too.
- 001
- 002
- ChangeMe!

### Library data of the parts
!PCB1 = PCB: Manufacturer: Any; PartNumber: TIDA-00400; SymbolCreator: a0412235
FID1-FID6 = Fiducial: Fiducial mark.  There is nothing to buy or mount.; SymbolCreator: codlsc
H1-H4 = NY PMS 440 0025 PH: Machine Screw, Round, #4-40 x 1/4, Nylon, Philips panhead; Manufacturer: B&F Fastener Supply; CompType: Hardware; SymbolCreator: codlsc; U/M: EA
H5-H8 = 1902C: Standoff, Hex, 0.5"L #4-40 Nylon; Manufacturer: Keystone; CompType: Hardware
LBL1 = THT-14-423-10: Thermal Transfer Printable Labels, 0.650" W x 0.200" H - 10,000 per roll; Manufacturer: Brady; SymbolCreator: a0412235; CompType: Label
Logo1 = TI_Logo: Texas Instrument Corporate Signature; SymbolCreator: codlsc
ZZ1 = AssemblyNoteLabel: SymbolCreator: a0412235
ZZ2-ZZ4 = AssemblyNote: SymbolCreator: codlsc

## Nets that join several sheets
+6.5V_ISO: Isolated_Flybuck_PS (L5.2 TP12.1), Post Regulated LDO (C28.1 C29.2 U4.5 U4.8)
+19V_ISO: Isolated_Flybuck_PS (L3.2 TP9.1), Post Regulated LDO (C18.1 U3.13 U3.15 U3.16)
-19V_ISO: Isolated_Flybuck_PS (L4.2 TP14.1), Post Regulated LDO (C22.1 C24.2 U5.5 U5.8)
SGND: Isolated_Flybuck_PS (7 pins), Post Regulated LDO (40 pins)

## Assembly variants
001: not fitted FID1 FID2 FID3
